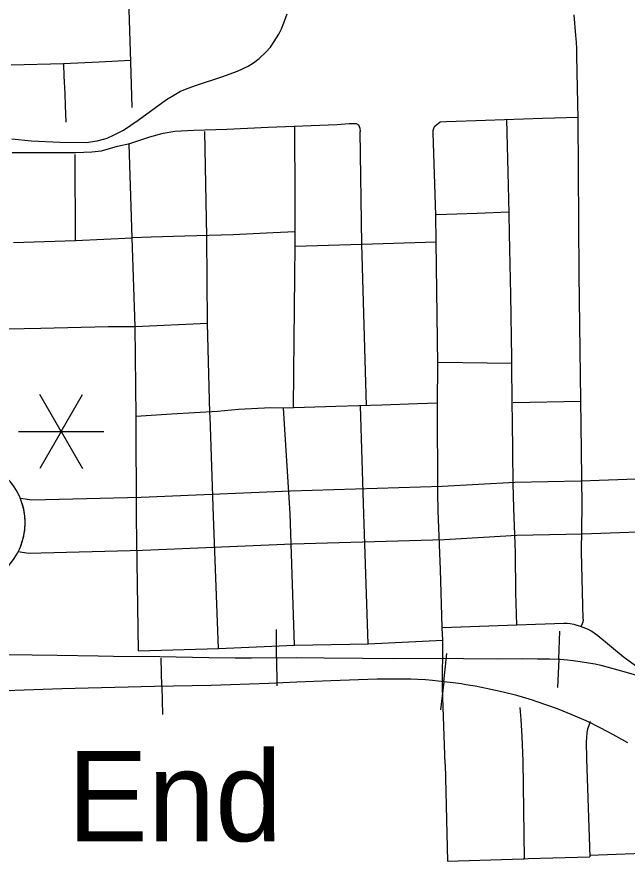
# Model space of a CAD drawing. Extents: x 309348 to 309445, y 336383 to 336484.
# Drawn here: x 309348.942 to 309349.513, y 336400.016 to 336400.809 of the extents above; entities that cross this region are included whole.
import ezdxf

# ---------------------------------------------------------------- set-up
doc = ezdxf.new("R2010")
doc.units = 0
doc.layers.add('R_Annotation', color=7, linetype='Continuous')

msp = doc.modelspace()

# ---------------------------------------------------------------- linework, layer by layer
at = {"layer": 'R_Annotation'}
for p, q in [((309348.98318, 336400.42052), (309348.96318, 336400.45518)), ((309348.98318, 336400.42052), (309349.00319, 336400.45518)), ((309348.94317, 336400.42052), (309348.98318, 336400.42052)), ((309348.98318, 336400.42052), (309348.96318, 336400.38587)), ((309348.98318, 336400.42052), (309349.0232, 336400.42052)), ((309348.98318, 336400.42052), (309349.00319, 336400.38587)), ((309349.18495, 336400.20876), (309349.18484, 336400.23516)), ((309349.44902, 336400.20718), (309349.45005, 336400.23357)), ((309349.07748, 336400.18176), (309349.07695, 336400.20816)), ((309349.18495, 336400.20876), (309349.18505, 336400.18235)), ((309349.34134, 336400.1862), (309349.34419, 336400.21246)), ((309349.44902, 336400.20718), (309349.448, 336400.1808)), ((309349.07748, 336400.18176), (309349.078, 336400.15535)), ((309349.34134, 336400.1862), (309349.33849, 336400.15995))]:
    msp.add_line(p, q, dxfattribs=at)
for points in [[(309349.0484, 336400.76663), (309349.04669, 336400.82528)], [(309348.937, 336400.69453), (309348.95542, 336400.69272), (309348.98189, 336400.69142), (309349.00654, 336400.69116), (309349.01692, 336400.69272), (309349.02626, 336400.69531), (309349.03275, 336400.69843), (309349.04157, 336400.70258), (309349.05532, 336400.71219), (309349.08179, 336400.7314), (309349.09009, 336400.7366), (309349.09502, 336400.73919), (309349.10203, 336400.74205), (309349.10982, 336400.74491), (309349.13369, 336400.7527), (309349.14822, 336400.75789), (309349.15834, 336400.76282), (309349.16327, 336400.76594), (309349.16872, 336400.76983), (309349.17495, 336400.77581), (309349.1791, 336400.78048), (309349.18247, 336400.78567), (309349.18688, 336400.79268), (309349.18948, 336400.79762), (309349.19155, 336400.80333), (309349.19467, 336400.81164)], [(309349.46716, 336400.71361), (309349.4667, 336400.74222), (309349.4662, 336400.75748), (309349.46608, 336400.77275), (309349.46599, 336400.77897), (309349.4657, 336400.78519), (309349.46518, 336400.7914), (309349.46348, 336400.81084)], [(309349.04836, 336400.76795), (309349.01862, 336400.76628), (309348.98522, 336400.765), (309348.93636, 336400.76347)], [(309348.988, 336400.71021), (309348.98722, 336400.72576), (309348.98687, 336400.73692), (309348.98595, 336400.75336), (309348.98569, 336400.76444)], [(309349.04982, 336400.72407), (309349.0484, 336400.76663)], [(309349.3335, 336400.70677), (309349.33795, 336400.71055), (309349.3441, 336400.71097), (309349.38039, 336400.71203), (309349.43386, 336400.71394), (309349.46713, 336400.71503)], [(309349.40259, 336400.6246), (309349.40213, 336400.65103), (309349.40044, 336400.71275)], [(309349.47021, 336400.40265), (309349.46809, 336400.56754), (309349.46716, 336400.71361)], [(309348.93741, 336400.68168), (309348.95599, 336400.68189), (309348.99694, 336400.68189), (309349.01201, 336400.68232), (309349.02092, 336400.68338), (309349.03599, 336400.68762), (309349.04745, 336400.69038), (309349.06612, 336400.69654), (309349.07864, 336400.69993), (309349.08946, 336400.70184), (309349.10729, 336400.70269), (309349.13827, 336400.70354), (309349.1771, 336400.70545), (309349.24161, 336400.708), (309349.25286, 336400.70885), (309349.25944, 336400.70885), (309349.26156, 336400.70758), (309349.26294, 336400.7047), (309349.26299, 336400.70136)], [(309349.20224, 336400.60658), (309349.20238, 336400.63866), (309349.20205, 336400.70644)], [(309349.33392, 336400.6232), (309349.33153, 336400.70029), (309349.3315, 336400.70057), (309349.33148, 336400.70085), (309349.33147, 336400.70113), (309349.33146, 336400.70141), (309349.33147, 336400.70169), (309349.33148, 336400.70196), (309349.33151, 336400.70224), (309349.33154, 336400.70252), (309349.33159, 336400.7028), (309349.33164, 336400.70307), (309349.3317, 336400.70334), (309349.33178, 336400.70361), (309349.33186, 336400.70388), (309349.33195, 336400.70414), (309349.33204, 336400.7044), (309349.33215, 336400.70466), (309349.33227, 336400.70492), (309349.33239, 336400.70517), (309349.33253, 336400.70541), (309349.33267, 336400.70565), (309349.33282, 336400.70589), (309349.33298, 336400.70612), (309349.33314, 336400.70634), (309349.33332, 336400.70656), (309349.3335, 336400.70677)], [(309349.11959, 336400.60312), (309349.11771, 336400.70153)], [(309349.26473, 336400.59609), (309349.26299, 336400.70136)], [(309349.04956, 336400.60186), (309349.04681, 336400.68952)], [(309348.99652, 336400.59944), (309348.99634, 336400.67997)], [(309349.40225, 336400.62586), (309349.37254, 336400.6248), (309349.33455, 336400.62331)], [(309349.33436, 336400.59812), (309349.33392, 336400.6232)], [(309349.40506, 336400.48449), (309349.40499, 336400.48918), (309349.40404, 336400.54841), (309349.40292, 336400.6059), (309349.40259, 336400.6246)], [(309348.99652, 336400.59944), (309349.04956, 336400.60186)], [(309349.20224, 336400.60759), (309349.18153, 336400.60648), (309349.14432, 336400.60482), (309349.09898, 336400.60352), (309349.06751, 336400.6026), (309349.04956, 336400.60186)], [(309349.0524, 336400.51895), (309349.04956, 336400.60186)], [(309349.12024, 336400.5219), (309349.11959, 336400.60312)], [(309349.20218, 336400.59417), (309349.20224, 336400.60658)], [(309348.93866, 336400.59766), (309348.99652, 336400.59944)], [(309349.20082, 336400.44273), (309349.201, 336400.47587), (309349.20206, 336400.56602), (309349.20218, 336400.59417)], [(309349.20218, 336400.59417), (309349.26473, 336400.59609)], [(309349.26473, 336400.59609), (309349.33436, 336400.59812)], [(309349.26895, 336400.44464), (309349.26473, 336400.59609)], [(309349.33578, 336400.48364), (309349.33436, 336400.59812)], [(309349.0524, 336400.51895), (309349.12024, 336400.5219)], [(309349.12252, 336400.4379), (309349.12024, 336400.5219)], [(309348.88132, 336400.51579), (309348.90115, 336400.51615), (309348.964, 336400.51727), (309349.02704, 336400.51877), (309349.0524, 336400.51895)], [(309349.05352, 336400.43466), (309349.0524, 336400.51895)], [(309349.33568, 336400.44649), (309349.33578, 336400.48364)], [(309349.33627, 336400.48537), (309349.40506, 336400.48449)], [(309349.40559, 336400.44646), (309349.40506, 336400.48449)], [(309349.19144, 336400.44248), (309349.17942, 336400.44265), (309349.1492, 336400.44097), (309349.12943, 336400.4393), (309349.08654, 336400.43668), (309349.05352, 336400.43466)], [(309349.33568, 336400.44694), (309349.31687, 336400.44657), (309349.28349, 336400.44508), (309349.24022, 336400.44377), (309349.19144, 336400.44248)], [(309349.26642, 336400.34315), (309349.26341, 336400.44447)], [(309349.3362, 336400.34627), (309349.33589, 336400.3627), (309349.33568, 336400.44649)], [(309349.40612, 336400.4013), (309349.40581, 336400.4307), (309349.40559, 336400.44646)], [(309349.46962, 336400.44857), (309349.4064, 336400.4475)], [(309349.05381, 336400.33956), (309349.05352, 336400.43466)], [(309349.12573, 336400.34136), (309349.12263, 336400.4343), (309349.12252, 336400.4379)], [(309349.19747, 336400.34378), (309349.19144, 336400.44248)], [(309349.40695, 336400.34873), (309349.40643, 336400.3719), (309349.40612, 336400.4013)], [(309349.4711, 336400.35095), (309349.47021, 336400.40265)], [(309348.94519, 336400.358), (309348.95575, 336400.3564), (309349.05809, 336400.3589), (309349.19806, 336400.365), (309349.33984, 336400.36917), (309349.40779, 336400.37293), (309349.46962, 336400.37442), (309349.84968, 336400.38801)], [(309348.94304, 336400.30774), (309348.94413, 336400.31026), (309348.94569, 336400.31404), (309348.94682, 336400.31734), (309348.94774, 336400.32067), (309348.94816, 336400.32247), (309348.94862, 336400.32484), (309348.94903, 336400.32762), (309348.94928, 336400.33007), (309348.94945, 336400.33286), (309348.94949, 336400.33541), (309348.94942, 336400.33794), (309348.94923, 336400.34062), (309348.94882, 336400.34399), (309348.94813, 336400.34775), (309348.94725, 336400.35133), (309348.94588, 336400.35558), (309348.94519, 336400.358)], [(309349.40843, 336400.30717), (309349.40832, 336400.31528), (309349.40695, 336400.34873)], [(309349.47046, 336400.30742), (309349.4711, 336400.35095)], [(309349.05552, 336400.21518), (309349.05381, 336400.33956)], [(309349.13038, 336400.21721), (309349.12573, 336400.34136)], [(309349.20178, 336400.22039), (309349.19747, 336400.34378)], [(309349.27054, 336400.22175), (309349.26642, 336400.34315)], [(309349.33778, 336400.30644), (309349.3362, 336400.34627)], [(309349.80265, 336400.33611), (309349.47111, 336400.32442), (309349.40978, 336400.32295), (309349.34196, 336400.31919), (309349.19989, 336400.31501), (309349.05979, 336400.30891), (309348.9526, 336400.30629), (309348.94304, 336400.30774)], [(309349.34004, 336400.23682), (309349.33837, 336400.29115), (309349.33778, 336400.30644)], [(309349.40979, 336400.23939), (309349.40896, 336400.26927), (309349.40843, 336400.30717)], [(309349.47011, 336400.2378), (309349.47133, 336400.24063), (309349.47144, 336400.24087), (309349.47154, 336400.2411), (309349.47164, 336400.24134), (309349.47172, 336400.24159), (309349.4718, 336400.24183), (309349.47187, 336400.24208), (309349.47193, 336400.24233), (309349.47198, 336400.24259), (309349.47202, 336400.24284), (309349.47206, 336400.2431), (309349.47208, 336400.24335), (309349.4721, 336400.24361), (309349.4721, 336400.24387), (309349.4721, 336400.24413), (309349.47209, 336400.24439), (309349.47207, 336400.24464), (309349.47143, 336400.27019), (309349.47046, 336400.30742)], [(309349.34004, 336400.23682), (309349.40979, 336400.23939)], [(309349.34055, 336400.22496), (309349.34005, 336400.23651), (309349.34004, 336400.23682)], [(309349.40979, 336400.23939), (309349.45382, 336400.24101), (309349.45698, 336400.24097), (309349.45978, 336400.24068), (309349.4631, 336400.24002), (309349.47011, 336400.2378)], [(309349.47011, 336400.2378), (309349.47078, 336400.23759), (309349.47508, 336400.23589), (309349.47988, 336400.2334), (309349.48562, 336400.22941), (309349.50943, 336400.20983), (309349.5209, 336400.2012), (309349.52671, 336400.19789), (309349.53288, 336400.19484), (309349.53432, 336400.19417), (309349.53577, 336400.19355), (309349.53724, 336400.19298), (309349.53874, 336400.19246), (309349.54025, 336400.192), (309349.54177, 336400.19159), (309349.54331, 336400.19123), (309349.54486, 336400.19092), (309349.55199, 336400.18978)], [(309349.20178, 336400.22039), (309349.27054, 336400.22175)], [(309349.27054, 336400.22175), (309349.34055, 336400.22496)], [(309349.34284, 336400.10894), (309349.34026, 336400.18006), (309349.34055, 336400.22496)], [(309349.05552, 336400.21518), (309349.13038, 336400.21721)], [(309349.13038, 336400.21721), (309349.20178, 336400.22039)], [(309348.92089, 336400.21178), (309348.92844, 336400.21152), (309348.95602, 336400.21135), (309348.9794, 336400.21102), (309349.01774, 336400.21034), (309349.0322, 336400.21001), (309349.07559, 336400.20967), (309349.12133, 336400.20883), (309349.14622, 336400.20866), (309349.16152, 336400.20866), (309349.20339, 336400.20883), (309349.22929, 336400.20866), (309349.26544, 336400.20833), (309349.29454, 336400.20799), (309349.34132, 336400.20816)], [(309348.92844, 336400.21152), (309348.95602, 336400.21135), (309348.9794, 336400.21102), (309349.01774, 336400.21034), (309349.0322, 336400.21001), (309349.07559, 336400.20967), (309349.12133, 336400.20883), (309349.14622, 336400.20866), (309349.16152, 336400.20866), (309349.20339, 336400.20883), (309349.22929, 336400.20866), (309349.26544, 336400.20833), (309349.29454, 336400.20799), (309349.34132, 336400.20816), (309349.36, 336400.20782), (309349.39148, 336400.20772), (309349.41509, 336400.20782), (309349.42905, 336400.20762), (309349.44027, 336400.20752), (309349.4504, 336400.20713), (309349.45728, 336400.20664), (309349.4625, 336400.20615), (309349.46909, 336400.20516), (309349.47706, 336400.20398), (309349.48306, 336400.2029), (309349.48847, 336400.20152), (309349.49535, 336400.19985), (309349.5045, 336400.19729), (309349.52093, 336400.19266)], [(309349.34132, 336400.20816), (309349.36, 336400.20782), (309349.39148, 336400.20772), (309349.41509, 336400.20782), (309349.42905, 336400.20762), (309349.44027, 336400.20752), (309349.4504, 336400.20713), (309349.45728, 336400.20664), (309349.4625, 336400.20615), (309349.46909, 336400.20516), (309349.47706, 336400.20398), (309349.48306, 336400.2029), (309349.48847, 336400.20152), (309349.49535, 336400.19985), (309349.5045, 336400.19729), (309349.52093, 336400.19266)], [(309349.51371, 336400.129), (309349.4996, 336400.13684), (309349.48848, 336400.14276), (309349.48292, 336400.14554), (309349.48079, 336400.14676), (309349.47887, 336400.14762), (309349.4772, 336400.14837), (309349.47478, 336400.14944), (309349.46234, 336400.1547), (309349.44788, 336400.16072), (309349.42786, 336400.16765), (309349.42437, 336400.16881), (309349.41522, 336400.17174), (309349.40994, 336400.17316), (309349.39697, 336400.17652), (309349.38281, 336400.17948), (309349.37068, 336400.18201), (309349.36214, 336400.18335), (309349.35791, 336400.18404), (309349.35026, 336400.1852), (309349.34137, 336400.1862), (309349.33071, 336400.18736), (309349.32421, 336400.18796), (309349.31705, 336400.18827), (309349.31044, 336400.18845), (309349.30546, 336400.18851), (309349.3003, 336400.18857), (309349.29387, 336400.18851), (309349.27897, 336400.18845), (309349.23578, 336400.18701), (309349.20388, 336400.18582), (309349.17776, 336400.18438), (309349.12367, 336400.18267), (309349.07064, 336400.18162), (309348.98387, 336400.17952), (309348.92214, 336400.17723)], [(309349.34137, 336400.1862), (309349.33071, 336400.18736), (309349.32421, 336400.18796), (309349.31705, 336400.18827), (309349.31044, 336400.18845), (309349.30546, 336400.18851), (309349.3003, 336400.18857), (309349.29387, 336400.18851), (309349.27897, 336400.18845), (309349.23578, 336400.18701), (309349.20388, 336400.18582), (309349.17776, 336400.18438), (309349.12367, 336400.18267), (309349.07064, 336400.18162), (309348.98387, 336400.17952), (309348.92214, 336400.17723)], [(309349.51371, 336400.129), (309349.4996, 336400.13684), (309349.48848, 336400.14276), (309349.48292, 336400.14554), (309349.48079, 336400.14676), (309349.47887, 336400.14762), (309349.4772, 336400.14837), (309349.47478, 336400.14944), (309349.46234, 336400.1547), (309349.44788, 336400.16072), (309349.42786, 336400.16765), (309349.42437, 336400.16881), (309349.41522, 336400.17174), (309349.40994, 336400.17316), (309349.39697, 336400.17652), (309349.38281, 336400.17948), (309349.37068, 336400.18201), (309349.36214, 336400.18335), (309349.35791, 336400.18404), (309349.35026, 336400.1852), (309349.34137, 336400.1862)], [(309349.41263, 336400.16211), (309349.41364, 336400.15088), (309349.41456, 336400.13472), (309349.41543, 336400.11166)], [(309349.47849, 336400.14896), (309349.47713, 336400.14528), (309349.4761, 336400.14174), (309349.47545, 336400.13853), (309349.47503, 336400.13357), (309349.47484, 336400.1303), (309349.47505, 336400.11398)], [(309349.41543, 336400.11166), (309349.41673, 336400.02034)], [(309349.47505, 336400.11398), (309349.4783, 336400.02213)], [(309349.34284, 336400.10894), (309349.34487, 336400.01807)], [(309349.66062, 336400.01629), (309349.65976, 336400.02457), (309349.65722, 336400.02732), (309349.65298, 336400.02987), (309349.64895, 336400.0305), (309349.63391, 336400.02966), (309349.55762, 336400.02669), (309349.51927, 336400.02499), (309349.47826, 336400.02327)], [(309349.34487, 336400.01807), (309349.41582, 336400.02031), (309349.41673, 336400.02034)], [(309349.41673, 336400.02034), (309349.42048, 336400.02046)], [(309349.42048, 336400.02046), (309349.4783, 336400.02213)]]:
    msp.add_lwpolyline(points, dxfattribs=at)
msp.add_arc((309348.88947, 336400.33506), 0.06002, 270, 90, dxfattribs=at)

# ---------------------------------------------------------------- texts
msp.add_text('End', height=0.084508, dxfattribs=at).set_placement((309348.98912, 336400.03678))

doc.saveas('drawing.dxf')
